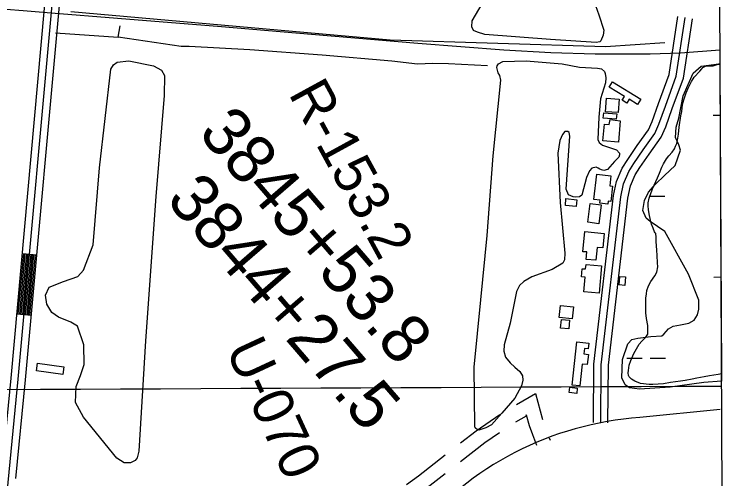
# Model space of a CAD drawing. Extents: x 3419139 to 3457078, y 540382 to 565875.
# Drawn here: x 3453441 to 3454925, y 551781 to 552735 of the extents above; entities that cross this region are included whole.
import ezdxf

# ---------------------------------------------------------------- set-up
doc = ezdxf.new("R2010")
doc.units = 0
for name, color, linetype in [('V-BLDG-OTLN', 7, 'Continuous'), ('V-GRID-FRAM', 7, 'Continuous'), ('V-GRID-MAJR', 7, 'Continuous'), ('V-RAIL-TRAK', 7, 'Continuous'), ('V-RIVR-RANG-IDEN', 7, 'Continuous'), ('V-ROAD-CNTR', 7, 'Continuous'), ('V-SITE-VEGE', 7, 'Continuous'), ('V-SURV-IDEN', 7, 'Continuous'), ('V-TOPO-SHOR', 7, 'Continuous'), ('V-WETL-SWMP', 7, 'Continuous')]:
    doc.layers.add(name, color=color, linetype=linetype)

msp = doc.modelspace()

# ---------------------------------------------------------------- linework, layer by layer
at = {"layer": 'V-BLDG-OTLN'}
for points in [[(3454672.2, 552596.3), (3454730.1, 552560.4), (3454723.6, 552549.9), (3454706.5, 552560.5), (3454701.6, 552552.6), (3454691.9, 552558.5), (3454696.5, 552565.9), (3454665.3, 552585.2)], [(3454685.4, 552560.8), (3454683.6, 552533.3), (3454657.8, 552535), (3454659.6, 552562.9)], [(3454653.9, 552532.9), (3454680.6, 552530.5), (3454679.5, 552519.3), (3454652.9, 552521.7)], [(3454688, 552516), (3454684.1, 552472.4), (3454652.4, 552475.3), (3454655.5, 552509.3), (3454665.1, 552508.4), (3454667, 552518.6)], [(3454639.9, 552406.3), (3454668.4, 552402.9), (3454666.3, 552382.8), (3454672, 552382.2), (3454668.8, 552350.6), (3454663.4, 552351.1), (3454662.7, 552345.1), (3454646, 552347.1), (3454646.7, 552353), (3454633.8, 552354.5)], [(3454576.2, 552356.4), (3454598.9, 552354), (3454597.5, 552340.2), (3454575.4, 552342.4)], [(3454644.2, 552304.7), (3454621.5, 552307.7), (3454626, 552346.6), (3454648.8, 552343.9)], [(3454611.1, 552246.7), (3454615.1, 552288.6), (3454654.6, 552284.9), (3454651.8, 552255.1), (3454640.3, 552256.2), (3454637.8, 552229.7), (3454618.1, 552231.5), (3454619.5, 552247.1)], [(3454649.5, 552217.9), (3454644.7, 552162), (3454613, 552164.8), (3454615.7, 552195.2), (3454608, 552195.8), (3454609.5, 552212.3), (3454616.7, 552211.7), (3454617.5, 552220.8)], [(3454697.4, 552178.1), (3454685.8, 552179), (3454686.9, 552196.1), (3454698.5, 552195.3)], [(3454591.5, 552133.8), (3454588.9, 552109.1), (3454562.1, 552111.9), (3454564.7, 552136.8)], [(3454566.9, 552108), (3454583.7, 552106.4), (3454582, 552089), (3454565, 552090)], [(3454598.6, 552061.8), (3454623.1, 552059), (3454621.9, 552047.5), (3454614.1, 552048.4), (3454612.9, 552037.1), (3454622.4, 552036.1), (3454620.2, 552015.2), (3454609.4, 552016.3), (3454604.7, 551971.3), (3454589.3, 551972.9)], [(3453542.9, 552010.4), (3453541, 551995), (3453486.6, 552002.7), (3453488.8, 552018.2)], [(3454584.3, 551968.7), (3454599.5, 551967), (3454598.3, 551956), (3454583.1, 551957.8)]]:
    msp.add_lwpolyline(points, close=True, dxfattribs=at)
at = {"layer": 'V-GRID-FRAM'}
msp.add_lwpolyline([(3423200.9, 563955.1), (3454837.9, 564093.1), (3454925.2, 545910.2), (3423272.3, 545772.1), (3423200.9, 563955.1)], dxfattribs=at)
at = {"layer": 'V-GRID-MAJR'}
msp.add_spline([(3423248.5, 551833.1), (3428523.1, 551854.2), (3433797.7, 551876), (3439072.3, 551898.7), (3444346.9, 551922.1), (3449621.5, 551946.2), (3454896.1, 551971.2)], degree=3, dxfattribs=at)
at = {"layer": 'V-RAIL-TRAK'}
for points in [[(3454811.8, 552655.3), (3454749.2, 552653.2), (3454636.5, 552653.2), (3454545.2, 552655.8), (3454448.5, 552661.3), (3454271.3, 552675.4), (3454052.8, 552693.8), (3453867.5, 552709.3), (3453653.8, 552726.6), (3453517.4, 552737.4), (3453459.7, 552742.3), (3453318.8, 552753.5), (3453114.5, 552770.6), (3452923.7, 552786.2), (3452689.8, 552805.5), (3452476.7, 552822.8)], [(3454892.8, 552661.4), (3454811.8, 552655.3)]]:
    msp.add_lwpolyline(points, dxfattribs=at)
at = {"layer": 'V-ROAD-CNTR'}
for p, q in [((3453457.8, 552243.8), (3453487.7, 552241.1)), ((3453446.5, 552119.3), (3453476.4, 552116.6)), ((3454541.8, 551865), (3454543.7, 551860.1))]:
    msp.add_line(p, q, dxfattribs=at)
for points in [[(3453343.2, 550823.7), (3453344.4, 550930), (3453379, 551270.2), (3453449.5, 551985.5), (3453525.2, 552823.2), (3453567.1, 553344.9), (3453572.2, 553383.2), (3453581, 553413.4), (3453591.7, 553439.5), (3453616, 553481.4), (3453658.6, 553543.1), (3453688, 553594.5), (3453720.1, 553656.5), (3453724.1, 553674.2), (3453736, 553771.9), (3453793.6, 554410.9), (3453851.2, 555091.5), (3453909.6, 555747.5), (3453945.8, 556130), (3453974.9, 556467.7), (3454011.8, 556908.2), (3454080.8, 557648.6)], [(3453444.4, 551781), (3453464.5, 551984.1), (3453540.1, 552821.9), (3453582, 553343.3), (3453586.9, 553380), (3453595.2, 553408.4), (3453605.2, 553432.9), (3453628.7, 553473.4), (3453671.3, 553535.1), (3453701.2, 553587.3), (3453734.3, 553651.3), (3453738.9, 553671.6), (3453740, 553681)], [(3453414.6, 551783.9), (3453434.6, 551987), (3453510.3, 552824.4), (3453552.2, 553346.5), (3453557.5, 553386.3), (3453566.9, 553418.3), (3453578.2, 553446.2), (3453603.3, 553489.5), (3453645.9, 553551.1), (3453674.9, 553601.7), (3453691.9, 553634.6)], [(3454632.7, 551896), (3454633.8, 552015.9), (3454674.1, 552362.6), (3454680.4, 552391.4), (3454692, 552419.2), (3454703.4, 552436.9), (3454723, 552465.2), (3454745.9, 552497.7), (3454753.7, 552515.1), (3454766.6, 552551.7), (3454788.7, 552611.6), (3454806.7, 552730.6)], [(3454647.7, 551895.8), (3454648.8, 552015), (3454688.9, 552360.1), (3454694.8, 552386.9), (3454705.3, 552412.2), (3454715.9, 552428.6), (3454735.3, 552456.6), (3454759, 552490.2), (3454767.6, 552509.5), (3454780.8, 552546.6), (3454803.3, 552607.8), (3454821.5, 552728.4)], [(3454662.7, 551895.7), (3454663.8, 552014), (3454703.7, 552357.6), (3454709.2, 552382.4), (3454718.7, 552405.2), (3454728.4, 552420.2), (3454747.6, 552448), (3454772.1, 552482.8), (3454781.6, 552503.9), (3454794.9, 552541.5), (3454817.9, 552604.1), (3454836.3, 552726.1)], [(3453449.5, 552119), (3453460.8, 552243.5)], [(3453452.5, 552118.8), (3453463.8, 552243.3)], [(3453455.5, 552118.5), (3453466.8, 552243)], [(3453458.5, 552118.2), (3453469.7, 552242.7)], [(3453461.5, 552118), (3453472.7, 552242.5)], [(3453464.5, 552117.7), (3453475.7, 552242.2)], [(3453467.5, 552117.4), (3453478.7, 552241.9)], [(3453470.4, 552117.2), (3453481.7, 552241.7)], [(3453473.4, 552116.9), (3453484.7, 552241.4)], [(3454474.8, 551933.1), (3454513.5, 551955.6), (3454523.2, 551920.3), (3454528.2, 551902.6)], [(3454893.8, 551922.9), (3454728.2, 551906.5)], [(3454359.4, 551854.2), (3454391.6, 551879.1), (3454440.3, 551912.9)], [(3454473, 551897.3), (3454494.9, 551910.1), (3454494.3, 551912.2), (3454500.6, 551890.2), (3454507.2, 551871.8), (3454515.6, 551849.5)], [(3454359.1, 551816), (3454409.3, 551854.9), (3454439.3, 551875.7)], [(3454248.4, 551768.9), (3454272.5, 551786.3), (3454327.7, 551829.7)], [(3454247.7, 551731.3), (3454248.1, 551731.7), (3454290.5, 551762.4), (3454327.6, 551791.4)]]:
    msp.add_lwpolyline(points, dxfattribs=at)
msp.add_arc((3454774.9, 551244.9), 663.2, 94.035, 140.5151, dxfattribs=at)
at = {"layer": 'V-SITE-VEGE'}
for p, q in [((3454878.9, 552629.4), (3454887.4, 552631.8)), ((3454887.4, 552631.8), (3454892.9, 552632.6)), ((3454892.9, 552632.6), (3454896, 551996)), ((3454840.2, 552605.9), (3454851.4, 552618.5)), ((3454851.4, 552618.5), (3454856.1, 552623.4)), ((3454856.1, 552623.4), (3454857.5, 552625.9)), ((3454857.5, 552625.9), (3454863.6, 552628.2)), ((3454863.6, 552628.2), (3454871.1, 552629.2)), ((3454871.1, 552629.2), (3454878.9, 552629.4)), ((3454834.8, 552597.2), (3454840.2, 552605.9)), ((3454827.5, 552583.1), (3454834.8, 552597.2)), ((3454818.6, 552559.2), (3454823.8, 552573.6)), ((3454823.8, 552573.6), (3454827.5, 552583.1)), ((3454816, 552549.6), (3454818.6, 552559.2)), ((3454814.3, 552535.2), (3454816, 552549.6)), ((3454812.4, 552526.3), (3454814.3, 552535.2)), ((3454809.2, 552503.3), (3454812.4, 552526.3)), ((3454807.5, 552488.9), (3454809.2, 552503.3)), ((3454806.4, 552480.7), (3454807.5, 552488.9)), ((3454801.8, 552463.8), (3454804.1, 552469.8)), ((3454804.1, 552469.8), (3454806.4, 552480.7)), ((3454794.9, 552451.9), (3454799.3, 552458.5)), ((3454799.3, 552458.5), (3454801.8, 552463.8)), ((3454776.8, 552427.7), (3454783, 552438.2)), ((3454783, 552438.2), (3454787.7, 552444.2)), ((3454787.7, 552444.2), (3454794.9, 552451.9)), ((3454773.2, 552420.7), (3454776.8, 552427.7)), ((3454764.3, 552399.2), (3454768.4, 552408.7)), ((3454768.4, 552408.7), (3454773.2, 552420.7)), ((3454754, 552376.3), (3454764.3, 552399.2)), ((3454747.7, 552357), (3454750, 552365.1)), ((3454750, 552365.1), (3454754, 552376.3)), ((3454745.4, 552347.4), (3454747.7, 552357)), ((3454745.3, 552341.1), (3454745.4, 552347.4)), ((3454745.9, 552334), (3454745.3, 552341.1)), ((3454747.2, 552325.1), (3454745.9, 552334)), ((3454750.5, 552311.9), (3454747.2, 552325.1)), ((3454752.2, 552303.8), (3454750.5, 552311.9)), ((3454755.6, 552295.9), (3454752.2, 552303.8)), ((3454758.7, 552288.1), (3454755.6, 552295.9)), ((3454759.7, 552286.3), (3454758.7, 552288.1)), ((3454761.1, 552284.8), (3454759.7, 552286.3)), ((3454761.7, 552277), (3454761.1, 552284.8)), ((3454761.9, 552268.2), (3454761.7, 552277)), ((3454763, 552250.5), (3454761.9, 552268.2)), ((3454763.9, 552239.1), (3454763, 552250.5)), ((3454764.7, 552224.6), (3454763.9, 552239.1)), ((3454763.4, 552205.5), (3454765, 552216.1)), ((3454765, 552216.1), (3454764.7, 552224.6)), ((3454759.4, 552197.7), (3454763.4, 552205.5)), ((3454746.3, 552177.4), (3454751, 552185.8)), ((3454751, 552185.8), (3454759.4, 552197.7)), ((3454742.9, 552167.2), (3454746.3, 552177.4)), ((3454740.9, 552151.6), (3454741.8, 552160.8)), ((3454741.8, 552160.8), (3454742.9, 552167.2)), ((3454740.4, 552121.9), (3454740.9, 552151.6)), ((3454742, 552109.8), (3454740.4, 552121.9)), ((3454744.6, 552095.6), (3454742, 552109.8)), ((3454744.4, 552077.5), (3454744.9, 552088.5)), ((3454744.9, 552088.5), (3454744.6, 552095.6)), ((3454732.1, 552063.2), (3454740.7, 552071.6)), ((3454740.7, 552071.6), (3454744.4, 552077.5)), ((3454715.7, 552037.9), (3454727, 552057.3)), ((3454727, 552057.3), (3454732.1, 552063.2)), ((3454709.8, 552023.9), (3454715.7, 552037.9)), ((3454706.1, 552014), (3454709.8, 552023.9)), ((3454704.6, 552003.1), (3454706.1, 552014)), ((3454704.1, 551998.1), (3454704.6, 552003.1)), ((3454705.1, 551993.1), (3454704.1, 551998.1)), ((3454706.5, 551989.9), (3454705.1, 551993.1)), ((3454889.7, 551995.2), (3454871.6, 551992.3)), ((3454896, 551996), (3454889.7, 551995.2)), ((3454711, 551985.2), (3454706.5, 551989.9)), ((3454717.7, 551981.2), (3454711, 551985.2)), ((3454729.3, 551976.5), (3454717.7, 551981.2)), ((3454791.3, 551978.7), (3454776.7, 551975.7)), ((3454811.9, 551981.2), (3454791.3, 551978.7)), ((3454821.8, 551982.8), (3454811.9, 551981.2)), ((3454835.7, 551985.4), (3454821.8, 551982.8)), ((3454845.3, 551987.4), (3454835.7, 551985.4)), ((3454860.6, 551990), (3454845.3, 551987.4)), ((3454871.6, 551992.3), (3454860.6, 551990)), ((3454747.3, 551974.4), (3454729.3, 551976.5)), ((3454755.1, 551974.3), (3454747.3, 551974.4)), ((3454776.7, 551975.7), (3454755.1, 551974.3))]:
    msp.add_line(p, q, dxfattribs=at)
msp.add_lwpolyline([(3454633.7, 552762.8), (3454644.2, 552734.2), (3454654, 552702.6), (3454653.1, 552692.3), (3454648.1, 552680.7), (3454645.8, 552678.5), (3454638.6, 552677.3), (3454544.2, 552683.5), (3454409.5, 552693.9), (3454394, 552698.1), (3454386.3, 552702.1), (3454382.3, 552709.6), (3454383.4, 552721.6), (3454417.8, 552780.8)], dxfattribs=at)
for points in [[(3453749.8, 552568.3), (3453732.6, 552360.7), (3453711.3, 552064.1), (3453697.6, 551837.1), (3453694.2, 551823.6), (3453690.2, 551817.8), (3453680.4, 551813.5), (3453667.5, 551813), (3453652.2, 551823), (3453583.9, 551907.5), (3453567, 551937.5), (3453568.3, 551970.4), (3453577.7, 551992.8), (3453585.2, 552015.3), (3453584.6, 552056), (3453571.1, 552094.3), (3453557.7, 552102.3), (3453532, 552112.4), (3453518.6, 552122.3), (3453507.9, 552139.3), (3453505.7, 552158), (3453513.1, 552174.1), (3453542.3, 552186.2), (3453572.2, 552196), (3453583.4, 552209.3), (3453603.7, 552261.3), (3453616.8, 552419.4), (3453639.8, 552622.5), (3453645.1, 552631.4), (3453653, 552637.1), (3453676.9, 552639.2), (3453727.8, 552629.3), (3453743.8, 552620.6), (3453750, 552609.5)], [(3454388.6, 551887.8), (3454387.5, 552010.2), (3454400.9, 552148), (3454413.8, 552280.2), (3454426.4, 552444.1), (3454442.4, 552599.9), (3454439.9, 552609.3), (3454436.5, 552614.8), (3454434.1, 552625.5), (3454434.5, 552629.1), (3454437.1, 552633.6), (3454446.3, 552637.9), (3454494.7, 552639.3), (3454568.3, 552633.2), (3454604.4, 552626.4), (3454641.2, 552624.2), (3454649.5, 552623.1), (3454655.3, 552617.5), (3454657.1, 552613.2), (3454658.3, 552604.8), (3454657.4, 552594.5), (3454647.5, 552561.4), (3454644.2, 552523.6), (3454642.1, 552477.5), (3454644.3, 552471.6), (3454651.3, 552466), (3454680.5, 552456.5), (3454686.2, 552449.9), (3454686.5, 552446), (3454685.1, 552441.5), (3454676.2, 552432.3), (3454661.7, 552416.1), (3454654, 552414.3), (3454649.5, 552415.3), (3454645.6, 552416.7), (3454642.7, 552419), (3454638.6, 552421), (3454629.8, 552418.6), (3454624.5, 552413.5), (3454618.8, 552400), (3454609.1, 552363.7), (3454604.2, 552360.2), (3454596.1, 552359.1), (3454591, 552360.1), (3454581.7, 552364.2), (3454576.7, 552375.9), (3454584.1, 552484.6), (3454582.6, 552492.1), (3454580.4, 552494.1), (3454573.6, 552494.2), (3454569.3, 552488.1), (3454563.9, 552475.6), (3454559.6, 552449.5), (3454564.3, 552348.3), (3454573.8, 552244.1), (3454573.2, 552230.6), (3454569.5, 552223.5), (3454547.7, 552211), (3454506, 552195.6), (3454489.7, 552186.1), (3454480.5, 552177.6), (3454474.5, 552165.7), (3454461.1, 552100.4), (3454449.3, 552056), (3454448.1, 552042.5), (3454451.8, 552030.8), (3454461.3, 552019), (3454471.1, 552009.7), (3454481.6, 552001.2), (3454486.7, 551992.4), (3454487.5, 551983.3), (3454485, 551971.4), (3454470.7, 551946.1), (3454444, 551915.2), (3454422.9, 551891.7), (3454411.1, 551885.1), (3454397.2, 551880.8), (3454393.9, 551881.5), (3454389.2, 551885.2)]]:
    msp.add_lwpolyline(points, close=True, dxfattribs=at)
at = {"layer": 'V-TOPO-SHOR'}
for p, q in [((3453655, 552688.3), (3453659.3, 552711.3)), ((3453526, 552697.1), (3453655, 552688.3))]:
    msp.add_line(p, q, dxfattribs=at)
for points in [[(3453557.7, 552740.7), (3454214.5, 552682.5), (3454435.9, 552675.8), (3454657.3, 552669.2), (3454779.4, 552677.3)], [(3454415, 552629.3), (3454334.4, 552633.4), (3454302.1, 552634), (3454270.7, 552632.7), (3454218, 552639), (3454074.7, 552651.4), (3453926.1, 552662.1), (3453800.8, 552668.8), (3453784.6, 552669), (3453655, 552688.3)]]:
    msp.add_lwpolyline(points, dxfattribs=at)
at = {"layer": 'V-WETL-SWMP'}
for p, q in [((3454854.1, 552628.7), (3454890.6, 552633.4)), ((3454890.6, 552633.4), (3454892.9, 552634)), ((3454892.9, 552634), (3454896.1, 551981.1)), ((3454837.7, 552614.1), (3454854.1, 552628.7)), ((3454817.5, 552567.3), (3454837.7, 552614.1)), ((3454808.3, 552521.5), (3454817.5, 552567.3)), ((3454879, 552527.9), (3454893.4, 552527.9)), ((3454802.8, 552502.9), (3454808.3, 552521.5)), ((3454801.8, 552482.2), (3454802.8, 552502.9)), ((3454808.6, 552467.2), (3454801.8, 552482.2)), ((3454811.7, 552456.2), (3454808.6, 552467.2)), ((3454800.8, 552424.1), (3454811.7, 552456.2)), ((3454779.1, 552403.8), (3454800.8, 552424.1)), ((3454760.7, 552386), (3454779.1, 552403.8)), ((3454746.2, 552369.4), (3454760.7, 552386)), ((3454738.1, 552352.8), (3454746.2, 552369.4)), ((3454734.5, 552332.1), (3454738.1, 552352.8)), ((3454747.7, 552361.1), (3454779.7, 552361.3)), ((3454741.3, 552316.5), (3454734.5, 552332.1)), ((3454749.6, 552309.3), (3454741.3, 552316.5)), ((3454779.6, 552288.7), (3454749.6, 552309.3)), ((3454828.5, 552201.2), (3454779.6, 552288.7)), ((3454849.6, 552147.8), (3454828.5, 552201.2)), ((3454880.4, 552195.2), (3454895, 552195.3)), ((3454849.4, 552129.1), (3454849.6, 552147.8)), ((3454846.6, 552117.6), (3454849.4, 552129.1)), ((3454840, 552106.7), (3454846.6, 552117.6)), ((3454796.5, 552094.2), (3454811.7, 552097.2)), ((3454811.7, 552097.2), (3454829.2, 552100.4)), ((3454829.2, 552100.4), (3454840, 552106.7)), ((3454777.8, 552077.8), (3454787.4, 552088.9)), ((3454787.4, 552088.9), (3454796.5, 552094.2)), ((3454703.6, 552058.1), (3454711.5, 552066.7)), ((3454711.5, 552066.7), (3454724.1, 552069.7)), ((3454724.1, 552069.7), (3454750.6, 552072.8)), ((3454750.6, 552072.8), (3454773.6, 552074.3)), ((3454773.6, 552074.3), (3454777.8, 552077.8)), ((3454692.3, 552025.4), (3454703.6, 552058.1)), ((3454691, 551988), (3454692.3, 552025.4)), ((3454701.2, 552028.2), (3454733.2, 552028.4)), ((3454749.2, 552028.5), (3454781.2, 552028.6)), ((3454697.9, 551973.6), (3454691, 551988)), ((3454860, 551978.2), (3454790.4, 551968.8)), ((3454896.1, 551981.1), (3454860, 551978.2)), ((3454707.1, 551967.3), (3454697.9, 551973.6)), ((3454727.7, 551964.4), (3454707.1, 551967.3)), ((3454790.4, 551968.8), (3454727.7, 551964.4))]:
    msp.add_line(p, q, dxfattribs=at)

# ---------------------------------------------------------------- texts
at = {"layer": 'V-RIVR-RANG-IDEN'}
for s, rotation, p in [('R-153.2', 298.6636, (3454004.4, 552572)), ('U-070', 294.7993, (3453874.9, 552046.7))]:
    msp.add_text(s, height=83, rotation=rotation, dxfattribs=at).set_placement(p)
at = {"layer": 'V-SURV-IDEN'}
for s, rotation, p in [('3845+53.8', 310.7669, (3453817.5, 552489.9)), ('3844+27.5', 310.7986, (3453751.4, 552352.9))]:
    msp.add_text(s, height=100, rotation=rotation, dxfattribs=at).set_placement(p)

doc.saveas('drawing.dxf')
